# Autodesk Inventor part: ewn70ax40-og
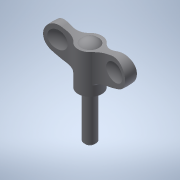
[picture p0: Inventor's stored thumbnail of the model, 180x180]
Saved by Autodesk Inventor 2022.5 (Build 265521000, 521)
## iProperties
Created: 2016-12
Part Number: ewn70ax40-og
Material: 一般
Document SubType Name: Modeling
Designer: imaocorp
Density: 1 g/cm^3
Appearance: 既定
Author: imaocorp
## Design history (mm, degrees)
node "ewn70ax40-og.x_t1"
node "ewn70ax40-og"
node "Base1"
